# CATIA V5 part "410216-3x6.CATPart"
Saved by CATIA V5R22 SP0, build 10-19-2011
Part number: 410216-3x6
Definition: 410216 VIS A TETE CYLINDRIQUE BOMBEE CRUCIFORME  "POZIDRIV" - INOX A4 - DIN 7985 - ISO 7045 - 410216-3X6
Description: 410216 VIS A TETE CYLINDRIQUE BOMBEE CRUCIFORME  "POZIDRIV" - INOX A4 - DIN 7985 - ISO 7045 - 410216-3X6
Property "REFERENCE": "410216-3X6"
Property "REFERENCE": "410216-3X6"
Property "SUPPLIER": "BENE INOX"
Property "SUPPLIER": "BENE INOX"
Property "DESIGN": "410216 VIS A TETE CYLINDRIQUE BOMBEE CRUCIFORME  \"POZIDRIV\" - INOX A4 - DIN 7985 - ISO 7045 - 410216-3X6"
Property "DESIGN": "410216 VIS A TETE CYLINDRIQUE BOMBEE CRUCIFORME  \"POZIDRIV\" - INOX A4 - DIN 7985 - ISO 7045 - 410216-3X6"
Property "TraceParts.PartNumber": "10-14012020-091350"
Property "TraceParts.PartTitle": "410216 VIS A TETE CYLINDRIQUE BOMBEE CRUCIFORME  \"POZIDRIV\" - INOX A4 - DIN 7985 - ISO 7045"
Property "TraceParts.InstanceId": "10-14012020-091350BOBQWTWAR7K2GUURUJ07SHH8Y"
Property "TRACEPARTS": "TRACEPARTS"
Property "TraceParts.PartLanguage": "fr"
Property "TraceParts.PartVersion": "1.0.8"
Bounding box of the stored display mesh (mm): x -2.362 to 6, y -2.663 to 2.663, z -2.8 to 2.8
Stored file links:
  U:\S9A\PER\CAO\Assemblage\Cadre\Chariot_X\410216-3x6.CATPart
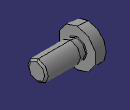
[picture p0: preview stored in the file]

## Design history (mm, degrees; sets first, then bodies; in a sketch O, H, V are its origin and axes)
AxisSystem1: origin (0, 0, 0), X (1, 0, 0), Y (0, 1, 0), Z (0, 0, 1)
Body1 "410216-3x6" (main body)
  Solid1: solid without history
